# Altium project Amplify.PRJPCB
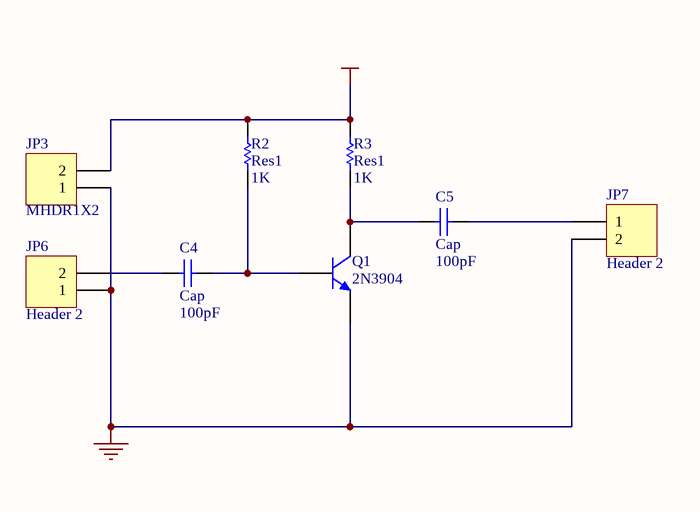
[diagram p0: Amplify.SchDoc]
1 sheet, 8 parts. Net scope: global (net labels, ports and power ports of the same name join across sheets).
Board file: Amplify.PCBDOC

## Sheet Amplify.SchDoc
size B

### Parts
C4  Cap  value 100pF  [RAD-0.3]
C5  Cap  value 100pF  [RAD-0.3]
JP3  MHDR1X2  [MHDR1X2]
JP6  Header 2  [HDR1X2]
JP7  Header 2  [HDR1X2]
Q1  2N3904  [BCY-W3/D4.7]
R2  Res1  value 1K  [AXIAL-0.3]
R3  Res1  value 1K  [AXIAL-0.3]

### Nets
GND: C4.1 JP3.1 JP6.1 JP6.2 JP7.2 Q1.1(E)
VCC: JP3.2 R2.2 R3.2
NetC4_2: C4.2 Q1.2(B) R2.1
NetC5_1: C5.1 Q1.3(C) R3.1
NetC5_2: C5.2 JP7.1

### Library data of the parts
C4 C5 = Cap: Capacitor; Manufacturer: Generic Components; Class I: Passive
JP3 = MHDR1X2: Header, 2-Pin; Manufacturer: Generic Components; Class I: Connector
JP6 JP7 = Header 2: Header, 2-Pin; Manufacturer: Generic Components; Class I: Connector
Q1 = 2N3904: NPN General Purpose Amplifier; Manufacturer: Generic Components; Revision 1: 11-July-2000: SIM Model Added.; Revision 2: July-2002: Re-released for DXP Platform.; Class I: Discrete; Class II: BJT - Low Power
R2 R3 = Res1: Resistor; Manufacturer: Generic Components; Class I: Passive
